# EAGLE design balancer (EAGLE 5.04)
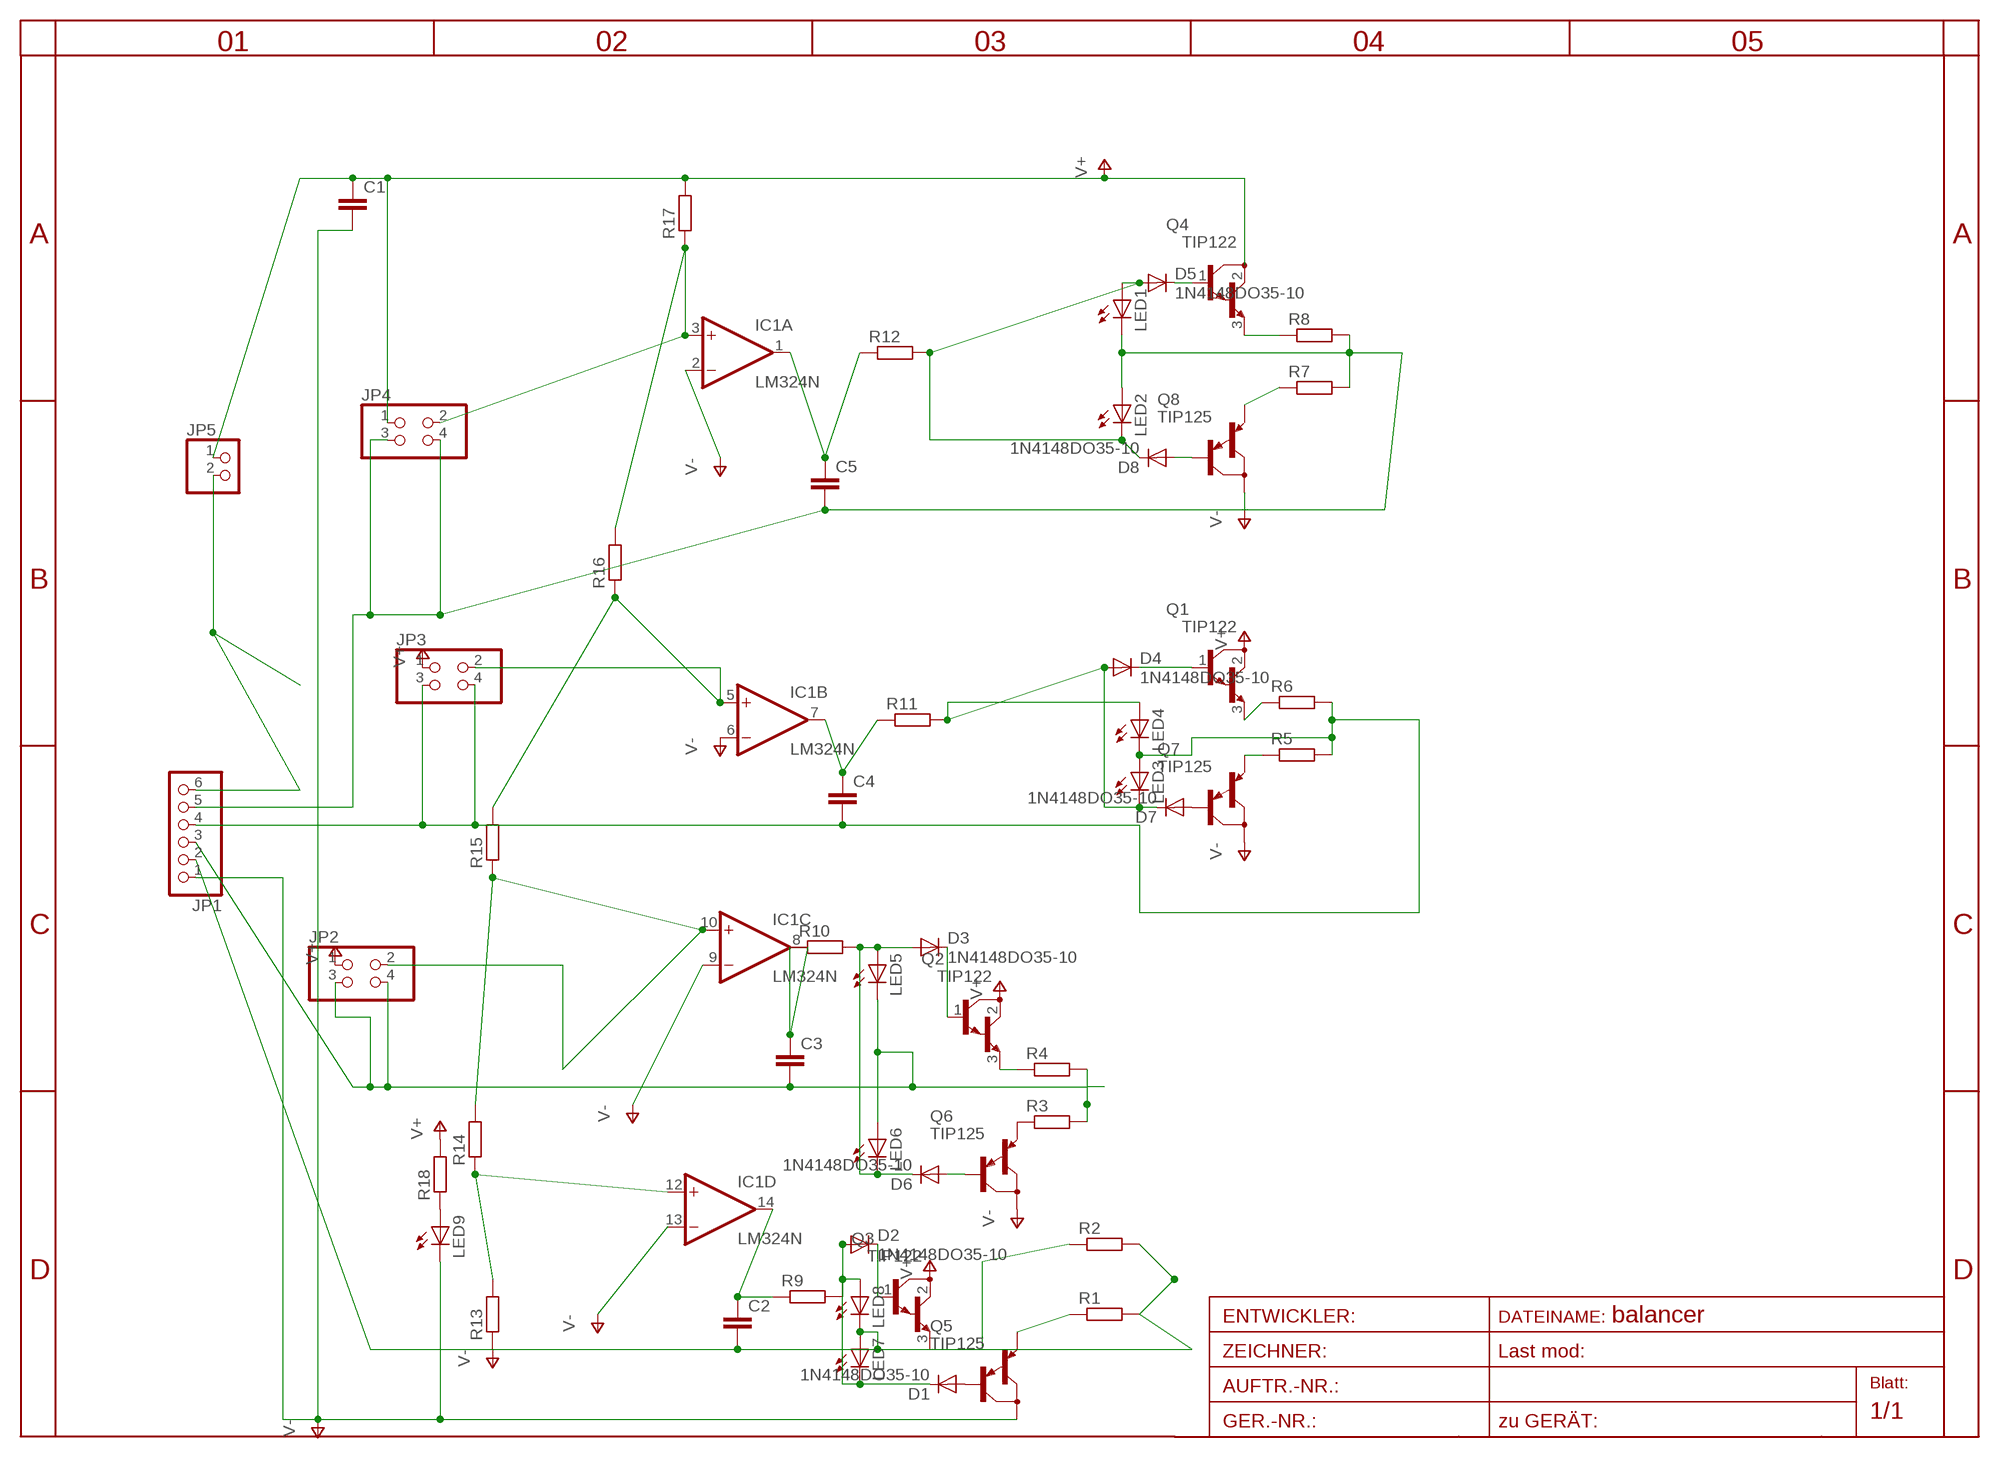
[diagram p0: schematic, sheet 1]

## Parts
C1  C-EU025-024X044  [C025-024X044]
C2  C-EU025-024X044  [C025-024X044]
C3  C-EU025-024X044  [C025-024X044]
C4  C-EU025-024X044  [C025-024X044]
C5  C-EU025-024X044  [C025-024X044]
D1  1N4148DO35-10  [DO35-10]
D2  1N4148DO35-10  [DO35-10]
D3  1N4148DO35-10  [DO35-10]
D4  1N4148DO35-10  [DO35-10]
D5  1N4148DO35-10  [DO35-10]
D6  1N4148DO35-10  [DO35-10]
D7  1N4148DO35-10  [DO35-10]
D8  1N4148DO35-10  [DO35-10]
IC1  LM324N  [DIL14]
JP1  PINHD-1X6  [1X06]
JP2  PINHD-2X2  [2X02]
JP3  PINHD-2X2  [2X02]
JP4  PINHD-2X2  [2X02]
JP5  PINHD-1X2  [1X02]
LED1  LED3MM  [LED3MM]
LED2  LED3MM  [LED3MM]
LED3  LED3MM  [LED3MM]
LED4  LED3MM  [LED3MM]
LED5  LED3MM  [LED3MM]
LED6  LED3MM  [LED3MM]
LED7  LED3MM  [LED3MM]
LED8  LED3MM  [LED3MM]
LED9  LED3MM  [LED3MM]
Q1  TIP122  [TO220]
Q2  TIP122  [TO220]
Q3  TIP122  [TO220]
Q4  TIP122  [TO220]
Q5  TIP125  [TO220]
Q6  TIP125  [TO220]
Q7  TIP125  [TO220]
Q8  TIP125  [TO220]
R1  R-EU_0207/10  [0207/10]
R2  R-EU_0207/10  [0207/10]
R3  R-EU_0207/10  [0207/10]
R4  R-EU_0207/10  [0207/10]
R5  R-EU_0207/10  [0207/10]
R6  R-EU_0207/10  [0207/10]
R7  R-EU_0207/10  [0207/10]
R8  R-EU_0207/10  [0207/10]
R9  R-EU_0207/30  [0207/30]
R10  R-EU_0207/10  [0207/10]
R11  R-EU_0207/20  [0207/20]
R12  R-EU_0207/10  [0207/10]
R13  R-EU_0204/5  [0204/5]
R14  R-EU_0204/5  [0204/5]
R15  R-EU_0204/5  [0204/5]
R16  R-EU_0204/5  [0204/5]
R17  R-EU_0204/5  [0204/5]
R18  R-EU_0207/10  [0207/10]

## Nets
N$1: D1.A Q5.1(B)
N$2: D2.C Q3.1(B)
N$3: D3.C Q2.1(B)
N$4: D4.C Q1.1(B)
N$5: D5.C Q4.1(B)
N$6: D6.A Q6.1(B)
N$7: D7.A Q7.1(B)
N$8: D8.A Q8.1(B)
N$9: D1.C D2.A LED7.K(C) LED8.A R9.2
N$10: D3.A D6.C LED5.A LED6.K(C) R10.2
N$11: D4.A D7.C LED3.K(C) LED4.A R11.2
N$12: D5.A D8.C LED1.A LED2.K(C) R12.2
N$13: Q5.3(E) R1.1
N$14: Q7.3(E) R5.1
N$15: Q1.3(E) R6.1
N$16: Q6.3(E) R3.1
N$17: Q2.3(E) R4.1
N$18: Q4.3(E) R8.1
N$19: Q8.3(E) R7.1
N$20: C5.1 IC1.1(A:OUT) R12.1
N$21: C4.1 IC1.7(B:OUT) R11.1
N$22: IC1.5(B:+IN) JP3.2 R15.2 R16.1
N$23: IC1.3(A:+IN) JP4.2 R16.2 R17.1
N$24: C3.1 IC1.8(C:OUT) R10.1
N$25: C2.1 IC1.14(D:OUT) R9.1
N$26: IC1.10(C:+IN) JP2.2 R14.2 R15.1
N$27: Q3.3(E) R2.1
N$28: IC1.12(D:+IN) R13.2 R14.1
N$29: JP1.6 JP5.2
N$30: C5.2 JP1.5 JP4.3 JP4.4 LED1.K(C) LED2.A R7.2 R8.2
N$33: C3.2 JP1.3 JP2.3 JP2.4 LED5.K(C) LED6.A R3.2 R4.2
N$34: LED9.A R18.1
N$38: C4.2 JP1.4 JP3.3 JP3.4 LED3.A LED4.K(C) R5.2 R6.2
N$39: C2.2 JP1.2 LED7.A LED8.K(C) R1.2 R2.2
V+: C1.1 JP2.1 JP3.1 JP4.1 JP5.1 Q1.2(C) Q2.2(C) Q3.2(C) Q4.2(C) R17.2 R18.2
V-: C1.2 IC1.2(A:-IN) IC1.6(B:-IN) IC1.9(C:-IN) IC1.13(D:-IN) JP1.1 LED9.K(C) Q5.2(C) Q6.2(C) Q7.2(C) Q8.2(C) R13.1

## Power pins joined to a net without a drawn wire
V+: IC1.4(P:V+)
V-: IC1.11(P:V-)

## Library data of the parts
C1-C5 = rcl-2:C-EU: CAPACITOR, European symbol
D1-D8 = diode-1:1N4148: DIODE
IC1 = linear:LM324: OP AMP
JP1 = pinhead:PINHD-1X6: PIN HEADER
JP2-JP4 = pinhead:PINHD-2X2: PIN HEADER
JP5 = pinhead:PINHD-1X2: PIN HEADER
LED1-LED9 = led:LED: LED
Q1-Q4 = transistor-npn:TIP122*: NPN Darlington Transistor
Q5-Q8 = transistor-pnp:TIP125: PNP Transistor
R1-R18 = rcl-2:R-EU_: RESISTOR, European symbol

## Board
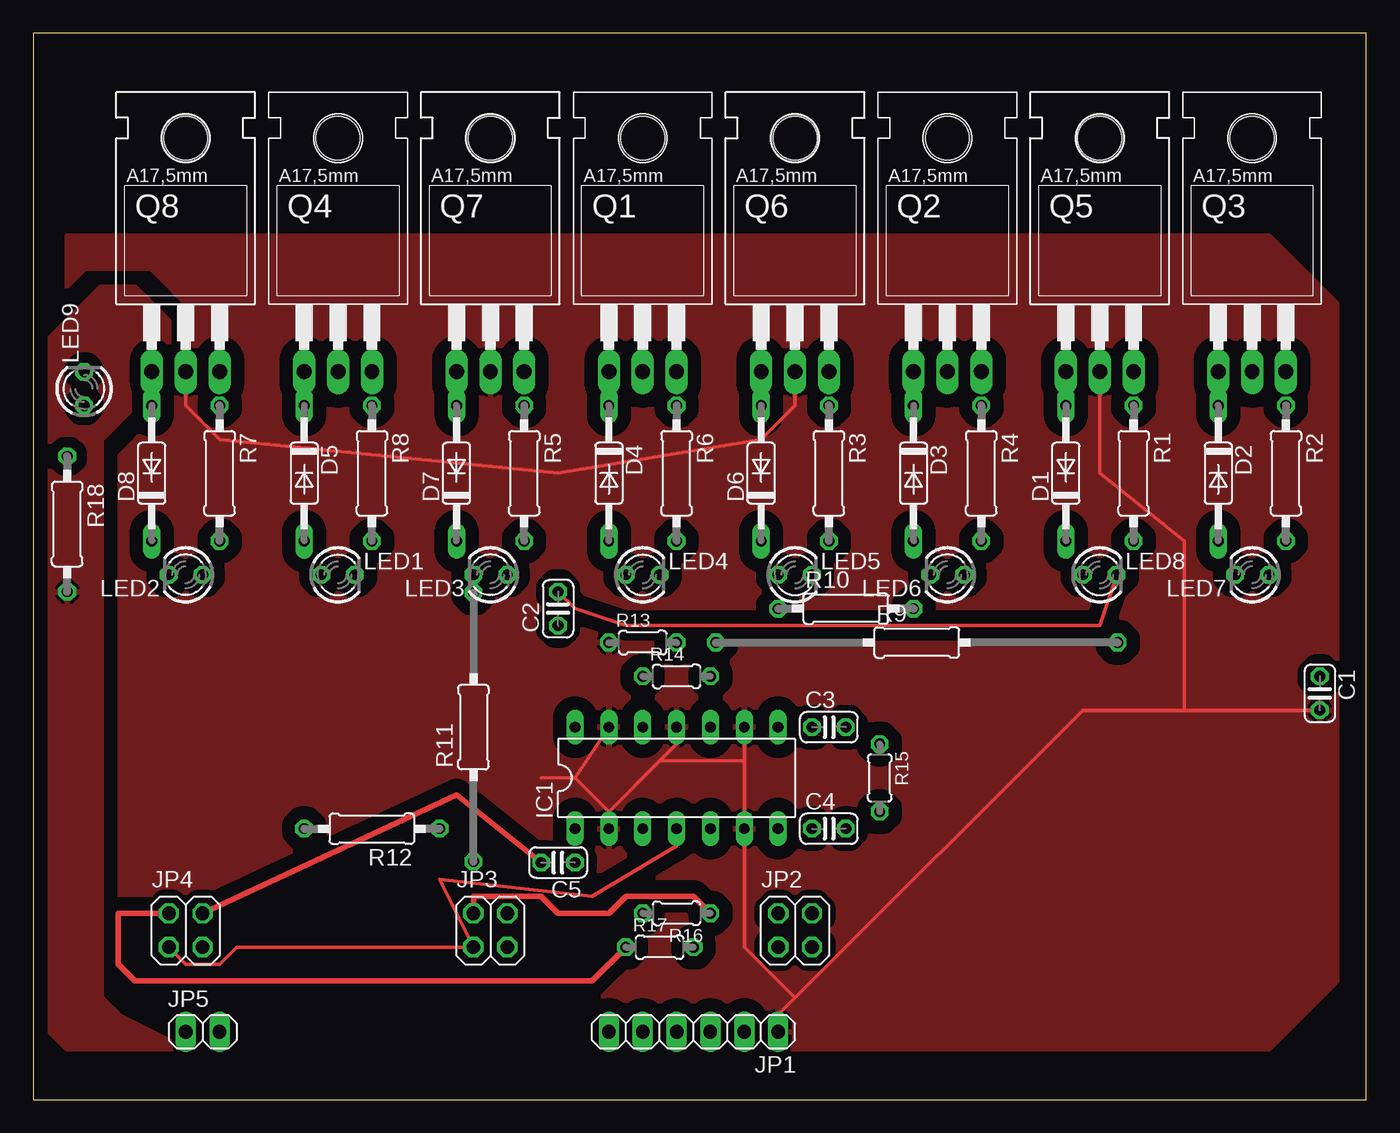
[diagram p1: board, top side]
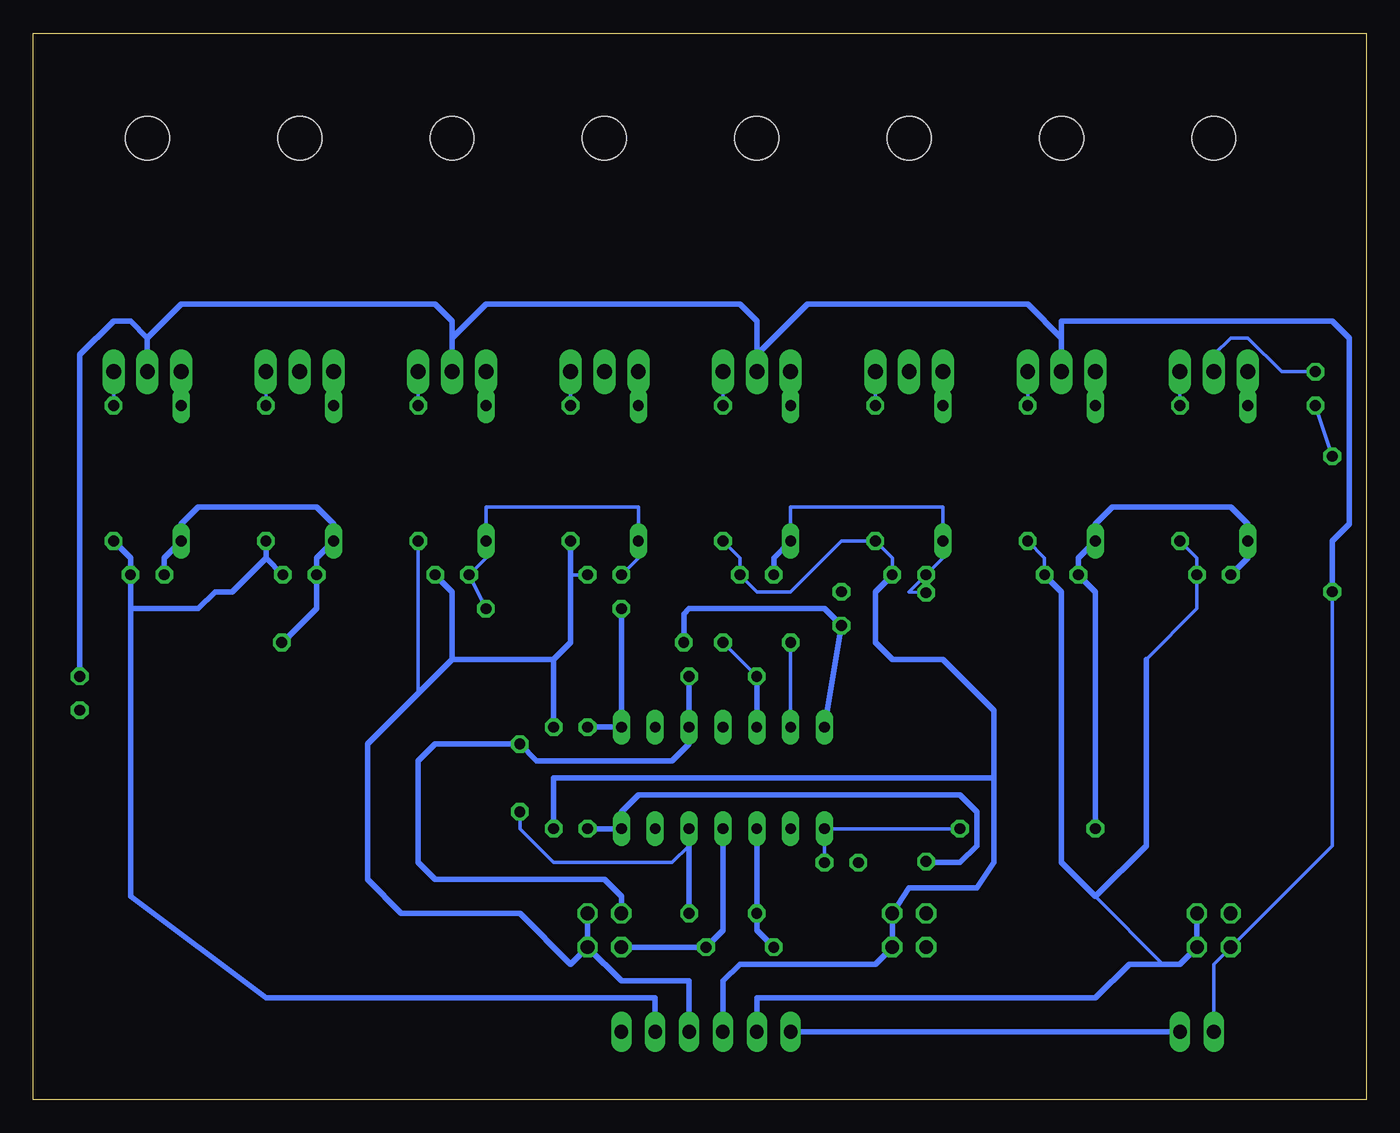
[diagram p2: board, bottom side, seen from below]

Size 100 x 80 mm. Coordinates in mm from the lower left corner, seen from the top.
Outline: 0,0 100,0 100,80 0,80 0,0
Copper layers (1*16): Top 0.035mm / dielectric 1.5mm / Bottom 0.035mm
Design rules "default": minimum track width 10mil, minimum drill 24mil, track to track 8mil, track to pad 8mil, pad to pad 8mil, via to via 8mil, smd to smd 8mil, copper to edge 40mil, drill to drill 8mil, minimum pad ring 10mil, minimum via ring 8mil, stop-mask expansion 4mil, vias tented up to drill 0mil, thermal gap 10mil

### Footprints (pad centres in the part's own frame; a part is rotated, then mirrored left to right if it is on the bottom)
C025-024X044 = drill 0.813 octagon: 1 -1.27,0; 2 1.27,0
DO35-10 = drill 0.813 long: A 5.08,0; C -5.08,0
DIL14 = drill 0.813 long: 1 -7.62,-3.81; 2 -5.08,-3.81; 3 -2.54,-3.81; 4 0,-3.81; 5 2.54,-3.81; 6 5.08,-3.81; 7 7.62,-3.81; 8 7.62,3.81; 9 5.08,3.81; 10 2.54,3.81; 11 0,3.81; 12 -2.54,3.81; 13 -5.08,3.81; 14 -7.62,3.81
1X06 = drill 1.016 long: 1 -6.35,0; 2 -3.81,0; 3 -1.27,0; 4 1.27,0; 5 3.81,0; 6 6.35,0
2X02 = drill 1.016 octagon: 1 -1.27,-1.27; 2 -1.27,1.27; 3 1.27,-1.27; 4 1.27,1.27
1X02 = drill 1.016 long: 1 -1.27,0; 2 1.27,0
LED3MM = drill 0.813 octagon: A -1.27,0; K 1.27,0
TO220 = drill 1.118 long: 1 -2.54,-6.35; 2 0,-6.35; 3 2.54,-6.35 | hole 3.302: 0,11.176
0207/10 = drill 0.813 octagon: 1 -5.08,0; 2 5.08,0
0207/30 = drill 0.813 octagon: 1 -15.08,0; 2 15.08,0
0207/20 = drill 0.813 octagon: 1 -10.08,0; 2 10.08,0
0204/5 = drill 0.813 octagon: 1 -2.54,0; 2 2.54,0

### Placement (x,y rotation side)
C1  96.52,30.48 270 top
C2  39.37,36.83 90 top
C3  59.69,27.94 0 top
C4  59.69,20.32 0 top
C5  39.37,17.78 180 top
D1  77.47,46.99 90 top
D2  88.9,46.99 270 top
D3  66.04,46.99 270 top
D4  43.18,46.99 270 top
D5  20.32,46.99 270 top
D6  54.61,46.99 90 top
D7  31.75,46.99 90 top
D8  8.89,46.99 90 top
IC1  48.26,24.13 0 top
JP1  49.53,5.08 180 top
JP2  57.15,12.7 0 top
JP3  34.29,12.7 0 top
JP4  11.43,12.7 0 top
JP5  12.7,5.08 0 top
LED1  22.86,39.37 0 top
LED2  11.43,39.37 180 top
LED3  34.29,39.37 180 top
LED4  45.72,39.37 0 top
LED5  57.15,39.37 0 top
LED6  68.58,39.37 180 top
LED7  91.44,39.37 180 top
LED8  80.01,39.37 0 top
LED9  3.81,53.34 90 top
Q1  45.72,60.96 0 top
Q2  68.58,60.96 0 top
Q3  91.44,60.96 0 top
Q4  22.86,60.96 0 top
Q5  80.01,60.96 0 top
Q6  57.15,60.96 0 top
Q7  34.29,60.96 0 top
Q8  11.43,60.96 0 top
R1  82.55,46.99 270 top
R2  93.98,46.99 270 top
R3  59.69,46.99 270 top
R4  71.12,46.99 270 top
R5  36.83,46.99 270 top
R6  48.26,46.99 270 top
R7  13.97,46.99 270 top
R8  25.4,46.99 270 top
R9  66.28,34.29 0 top
R10  60.96,36.83 0 top
R11  33.02,27.94 90 top
R12  25.4,20.32 180 top
R13  45.72,34.29 0 top
R14  48.26,31.75 0 top
R15  63.5,24.13 270 top
R16  48.26,13.97 180 top
R17  46.99,11.43 0 top
R18  2.54,43.18 270 top

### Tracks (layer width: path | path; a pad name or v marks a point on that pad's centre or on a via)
N$1
  Bottom 0.254: D1.A Q5.1
N$2
  Bottom 0.254: D2.C Q3.1
N$3
  Bottom 0.254: D3.C Q2.1
N$4
  Top 0.254: D4.C Q1.1
N$5
  Bottom 0.254: D5.C Q4.1
N$6
  Bottom 0.254: D6.A Q6.1
N$7
  Bottom 0.254: D7.A Q7.1
N$8
  Bottom 0.254: D8.A Q8.1
N$9
  Bottom 0.406: R9.2 81.28,34.29 78.74,36.83 LED8.A 78.74,40.64 D1.C 77.47,43.18 78.74,44.45 87.63,44.45 88.9,43.18 D2.A 90.17,40.64 LED7.K
N$10
  Bottom 0.254: LED5.A 54.61,40.64 D6.C 54.61,44.45 66.04,44.45 D3.A 66.04,40.64 LED6.K R10.2
N$11
  Bottom 0.254: R11.2 34.29,38.1 LED3.K 31.75,40.64 D7.C 31.75,44.45 43.18,44.45 D4.A
  Bottom 0.406: LED4.A 44.45,40.64 D4.A
N$12
  Bottom 0.406: R12.2 20.32,38.1 LED1.A 21.59,40.64 D5.A 20.32,43.18 19.05,44.45 10.16,44.45 8.89,43.18 D8.C 8.89,40.64 LED2.K
N$13
  Bottom 0.254: R1.1 Q5.3
N$14
  Bottom 0.254: R5.1 Q7.3
N$15
  Bottom 0.254: R6.1 Q1.3
N$16
  Bottom 0.254: R3.1 Q6.3
N$17
  Bottom 0.254: R4.1 Q2.3
N$18
  Bottom 0.254: R8.1 Q4.3
N$19
  Bottom 0.254: R7.1 Q8.3
N$20
  Bottom 0.254: R12.1 IC1.1 C5.1
N$21
  Bottom 0.406: R11.1 32.94,17.78 30.48,17.78 29.21,19.05 29.21,21.59 30.48,22.86 54.61,22.86 55.88,21.59 IC1.7 C4.1
N$22
  Top 0.406: JP3.2 33.02,15.24 38.1,15.24 39.37,13.97 43.18,13.97 44.45,15.24 49.53,15.24 R16.1
  Bottom 0.254: R15.2 63.5,20.32 60.96,17.78 52.07,17.78 50.8,19.05 IC1.5
  Bottom 0.406: R16.1 IC1.5
N$23
  Top 0.406: R17.1 41.91,8.89 7.62,8.89 6.35,10.16 6.35,13.97 JP4.2
  Bottom 0.406: IC1.3 R16.2 45.72,12.7 R17.1
N$24
  Bottom 0.406: R10.1 IC1.8 C3.1
N$25
  Bottom 0.406: IC1.14 C2.1 40.64,36.83 50.8,36.83 51.2,36.43 R9.1
N$26
  Bottom 0.406: JP2.2 55.88,15.24 57.15,16.51 69.85,16.51 71.12,17.78 71.12,25.4 69.85,26.67 R15.1 62.23,25.4 52.07,25.4 50.8,26.67 IC1.10 R14.2
N$27
  Bottom 0.254: R2.1 Q3.3
N$28
  Bottom 0.254: R14.1 R13.2
  Bottom 0.406: IC1.12 R14.1
N$29
  Bottom 0.406: JP5.2 JP1.6
N$30
  Top 0.254: JP1.5 45.72,6.35
  Top 0.406: C5.2 31.75,22.86 JP4.4
  Bottom 0.254: R7.2 12.7,40.64 LED2.A 12.7,36.83 16.51,33.02 | LED1.K 24.13,40.64 R8.2 | 15.24,10.16 20.32,15.24
  Bottom 0.406: 16.51,33.02 16.51,19.05 20.32,15.24 22.86,17.78 22.86,38.1 LED1.K | JP1.5 45.72,7.62 20.32,7.62 17.78,10.16 15.24,10.16 13.97,10.16 JP4.3 JP4.4
N$33
  Bottom 0.254: 59.69,39.37 LED5.K | 71.12,30.48 R4.2
  Bottom 0.406: JP1.3 50.8,8.89 55.88,8.89 JP2.3 | JP2.3 59.69,10.16 63.5,13.97 72.39,13.97 74.93,16.51 74.93,26.67 71.12,30.48 68.58,33.02 | 68.58,33.02 68.58,38.1 LED6.A | R3.2 59.69,39.37 59.69,34.29 60.96,33.02 | 68.58,33.02 60.96,33.02 | 60.96,33.02 C3.2 | JP2.3 JP2.4
N$34
  Bottom 0.254: R18.1 LED9.A
N$38
  Bottom 0.254: LED3.A 35.56,40.64 R5.2 39.37,41.91 43.18,38.1 45.72,38.1 LED4.K 46.99,40.64 R6.2
  Bottom 0.406: JP1.4 48.26,8.89 46.99,10.16 36.83,10.16 JP3.3 JP3.4 34.29,15.88 29.21,15.88 27.94,17.78 27.94,24.13 | 27.94,24.13 27.94,29.21 31.75,33.02 35.56,33.02 36.83,34.29 36.83,38.1 LED3.A | C4.2 60.96,24.13 27.94,24.13
N$39
  Top 0.254: C2.2 40.64,36.83 44.45,35.56 80.01,35.56 LED8.K
  Bottom 0.406: JP1.2 53.34,7.62 82.55,7.62 92.71,15.24 92.71,36.83 | 92.71,36.83 LED7.A 92.71,40.64 R2.2 | 82.55,40.64 R1.2 | 82.55,40.64 85.09,38.1 86.36,38.1 87.63,36.83 92.71,36.83 | 82.55,40.64 LED8.K
V+
  Top 0.254: IC1.4 48.26,19.05 41.91,15.24 30.48,16.51 JP3.1 15.24,11.43 13.97,10.16 11.43,10.16 JP4.1
  Bottom 0.254: R18.2 2.54,19.05 JP4.1 11.43,10.16 JP5.1
  Bottom 0.406: JP2.1 R17.2 48.26,12.7 IC1.4 | R18.2 2.54,41.91 1.27,43.18 1.27,57.15 2.54,58.42 22.86,58.42 Q4.2 22.86,57.15 25.4,59.69 41.91,59.69 45.72,55.88 Q1.2 45.72,58.42 46.99,59.69 66.04,59.69 68.58,57.15 Q2.2 68.58,58.42 69.85,59.69 88.9,59.69 91.44,57.15 | 91.44,57.15 Q3.2 | C1.1 96.52,55.88 93.98,58.42 92.71,58.42 91.44,57.15
  pour Top (isolate 0.813, rank 4): 11.43,3.81 2.54,3.81 1.27,5.08 1.27,57.15 5.08,60.96 7.62,60.96 10.16,58.42 10.16,53.34 8.89,52.07 7.62,52.07 5.08,49.53 5.08,7.62 6.35,6.35
V-
  Top 0.254: 53.34,25.4 IC1.6 53.34,11.43 57.15,7.62 | 53.34,25.4 IC1.9 | 43.18,21.59 40.64,24.13 | 40.64,24.13 IC1.13 | 46.99,25.4 43.18,21.59 | 46.99,25.4 48.26,26.67 IC1.11 | 43.18,21.59 IC1.2 | 40.64,24.13 38.1,24.13 | Q6.2 57.15,52.07 54.61,49.53 39.37,46.99 13.97,49.53 11.43,52.07 Q8.2 | 53.34,25.4 46.99,25.4 | 86.36,29.21 78.74,29.21 57.15,7.62 | 86.36,29.21 C1.2 | 57.15,7.62 55.88,6.35 JP1.1 | 86.36,29.21 86.36,41.91 80.01,46.99 Q5.2
  Bottom 0.254: LED9.K 6.35,54.61 8.89,57.15 10.16,57.15 11.43,55.88 Q8.2 | IC1.13 R13.1
  pour Top (isolate 1.016, rank 5): 2.54,64.77 92.71,64.77 97.79,59.69 97.79,8.89 92.71,3.81 3.81,3.81 2.54,5.08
